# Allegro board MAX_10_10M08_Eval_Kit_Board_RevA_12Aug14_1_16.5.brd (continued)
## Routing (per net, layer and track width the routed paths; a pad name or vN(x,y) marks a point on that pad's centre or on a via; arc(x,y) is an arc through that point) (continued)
LED1: length 41.6
  TOP w0.16: U2.132 21.85,48.75 21.35,48.25 18.75,48.25 16.3,45.8 16.3,37.3 6.7,27.7 D1.2
LED2: length 40.2
  TOP w0.16: U2.134 21.8,47.75 21.65,47.9 19,47.9 16.8,45.7 16.8,37.1 8.5,28.8 D2.2
LED3: length 39
  TOP w0.16: D3.2 10.3,29.9 17.3,36.9 17.3,45.6 19.25,47.55 21.45,47.55 21.75,47.25 U2.135
LED4: length 35.3
  TOP w0.16: U2.140 19.25,44.75 17.8,43.3 17.8,36.7 12.1,31 D4.2
LED5: length 34.1
  TOP w0.16: U2.141 21.85,44.25 21.7,44.4 19.6,44.4 18.3,43.1 18.3,36.5 13.9,32.1 D5.2
NCONFIG: length 73.1
  TOP w0.16: SW2.4 SW2.3 37.15,75.45 36.1,74.4 v1(11.3,74.4) ; v1(22.6,62.7) 24.4,60.9 24.4,58.6 25.1,57.9 25.1,51.2 24.15,50.25 U2.129 21.16,50.25 R53.1
  BOTTOM w0.16: v1(22.6,62.7) 19.9,65.4 15.1,65.4 11.3,69.2 v1(11.3,74.4)
Net_66: length 0.7
  L2_GND w1.2: 36.3,24.1 36.3,24.8
OSC_OUT: length 4.1
  TOP w0.16: U2.27 37.75,36.89 X1.3
RESET_N: length 182.9
  TOP w0.16: SW1.4 SW1.3 44.8,78.05 v1(44.8,76.8) 44.8,75.6 42.9,73.7 v1(10.6,73.7) ; v1(14.2,45) 14.2,49.1 17.45,52.35 20.35,52.35 21.11,53.11 R72.2 21.66,54.25 U2.121 24.15,54.25 24.7,54.8 24.7,57.7 24,58.4 24,60.5 v1(22.6,61.9)
  BOTTOM w0.16: v1(10.6,73.7) 10.6,69.1 14.7,65 19.5,65 v1(22.6,61.9) ; J2.3 27.41,22.61 25.8,21 13.2,21 10.3,23.9 10.3,41.1 v1(14.2,45) ; v1(44.8,76.8) 56.8,76.8 62,71.6 62,44.9 61.4,44.3 59.2,44.3 58.02,45.48 J11.5
SWITCH 1: length 90.3
  TOP w0.16: v1(18.7,53.5) 19.6,54.4 21.2,54.4 21.55,54.75 U2.120 ; v1(46.4,9.2) 46.4,10.86 SW3.12
  BOTTOM w0.16: v1(18.7,53.5) 17.4,53.5 7.9,44 7.9,22.1 12,18 40.3,18 41.8,16.5 41.8,11.9 44.5,9.2 v1(46.4,9.2) R69.2
SWITCH 2: length 90.5
  TOP w0.16: v1(15.4,48.4) 15.4,48.9 18.15,51.65 20.75,51.65 21.85,52.75 U2.124 ; v1(48.9,9.2) 48.9,10.9 SW3.11
  BOTTOM w0.16: R68.2 v1(48.9,9.2) 48.3,9.8 44.6,9.8 42.2,12.2 42.2,16.8 40.5,18.5 12.2,18.5 8.3,22.4 8.3,42.7 14,48.4 v1(15.4,48.4)
SWITCH 3: length 91
  TOP w0.16: U2.127 21.45,51.25 21.15,50.95 19.25,50.95 v1(16.1,47.8) ; v1(51.4,9.2) 51.4,10.88 SW3.10
  BOTTOM w0.16: R67.2 v1(51.4,9.2) 50.3,10.3 44.8,10.3 42.6,12.5 42.6,17.1 40.7,19 12.4,19 8.7,22.7 8.7,42.4 14.1,47.8 v1(16.1,47.8)
SWITCH 4: length 91.7
  TOP w0.16: SW3.9 53.9,10.84 v1(53.9,9.2) ; U2.130 21.75,49.75 20.95,48.95 18.25,48.95 16.5,47.2 v1(15.4,47.2)
  BOTTOM w0.16: R66.2 v1(53.9,9.2) 52.3,10.8 45,10.8 43,12.8 43,17.4 40.9,19.5 12.6,19.5 9.1,23 9.1,42.1 14.2,47.2 v1(15.4,47.2)
SWITCH 5: length 92.9
  TOP w0.16: SW3.8 56.5,10.9 v1(56.5,9.2) ; U2.131 21.8,49.25 21.15,48.6 18.5,48.6 16.5,46.6 v1(16.1,46.6)
  BOTTOM w0.16: R65.2 v1(56.5,9.2) 54.4,11.3 45.2,11.3 43.4,13.1 43.4,17.7 41.1,20 12.8,20 9.5,23.3 9.5,41.8 14.3,46.6 v1(16.1,46.6)
TCK: length 94.1
  TOP w0.16: U2.18 33.25,42.05 v1(33.3,42.1)
  BOTTOM w0.16: J10.1 R62.2 64.49,78.81 69,74.3 69,35.1 67.1,33.2 63.2,33.2 57.76,38.64 39.76,38.64 37.5,40.9 34,40.9 33.3,41.6 v1(33.3,42.1)
TDI: length 108.2
  TOP w0.16: v1(33.9,42.7) 33.9,41.9 33.75,41.75 U2.19 ; v1(67.2,75) 56.3,75 53.6,77.7 53.6,82.3 52.34,83.56 J10.9
  BOTTOM w0.16: J10.9 53.6,82.34 R54.1 ; v1(33.9,42.7) 33.9,41.7 34.35,41.25 37.65,41.25 39.94,38.96 58.04,38.96 63.4,33.6 66.9,33.6 68.6,35.3 68.6,73.6 v1(67.2,75)
TDO: length 90.6
  TOP w0.16: v1(34.5,42.1) 34.25,41.85 U2.20
  BOTTOM w0.16: v1(34.5,42.1) 35,41.6 37.8,41.6 40.12,39.28 58.32,39.28 63.6,34 66.7,34 68.2,35.5 68.2,73 61.26,79.94 61.26,82.3 J10.3
TMS: length 107.4
  TOP w0.16: J10.5 57.42,83.58 58.7,82.3 58.7,77.5 60,76.2 v1(69.1,76.2) ; U2.16 32.25,41.95 v1(32.1,42.1)
  BOTTOM w0.16: v1(69.1,76.2) 69.1,75.3 69.4,75 69.4,34.9 67.3,32.8 63,32.8 57.48,38.32 39.58,38.32 37.35,40.55 33.65,40.55 v1(32.1,42.1) ; R55.1 56.2,82.38 J10.5
VREF_2.5V: length 8.8
  TOP w0.28: U2.5 26.75,41.75 27,42 v1(27,42.8)
  BOTTOM w0.28: v1(27,42.8) 27,43.29 C12.2
  BOTTOM w0.35: C61.2 R74.2 ; C61.2 28.21,43.91 27.99,43.69 C12.2 ; C61.2 28.21,47.06 U5.2
VREFB1N0: length 56.3
  TOP w0.16: v1(32.7,42.7) 32.75,42.65 U2.17
  BOTTOM w0.16: J8.38 72.9,26.42 72.9,28.3 72.2,29 65.6,29 56.92,37.68 39.22,37.68 37.05,39.85 33.05,39.85 31,41.9 31,43 31.3,43.3 32.1,43.3 v1(32.7,42.7)
VREFB2N0: length 39.8
  TOP w0.16: U2.30 39.25,41.75 v1(38.8,42.2) ; v1(63.4,41) 66.5,44.2 72.84,44.2 J8.22
  BOTTOM w0.16: v1(38.8,42.2) 40.1,40.9 43.5,40.9 44,40.4 62.71,40.4 v1(63.4,41)
VREFB3N0: length 73
  TOP w0.16: U2.48 44.24,48.21 45.81,48.21 v1(46.3,48.7) ; J8.2 72.84,69.6 v1(66.3,69.6)
  BOTTOM w0.16: v1(46.3,48.7) 52.3,42.7 63.5,42.7 64.6,41.6 64.6,36.1 64.9,35.8 65.9,35.8 66.5,36.4 66.5,43 66.3,43.2 v1(66.3,69.6)
VREFB4N0: length 46.9
  TOP w0.16: v1(42.9,54.7) 42.95,54.75 U2.61 ; J8.33 72.9,31.56 72.9,33.4 72.2,34.1 68.7,34.1 v1(65.9,36.9)
  BOTTOM w0.16: v1(42.9,54.7) 53.7,43.9 64.1,43.9 65.9,42.1 v1(65.9,36.9)
VREFB5N0: length 138.2
  TOP w0.16: v1(46.5,72.5) 46.5,69.3 45.7,68.5 42.6,68.5 38.75,64.65 U2.80
  BOTTOM w0.16: J9.38 7.5,28.14 7.5,44.3 17.29,54.09 24.59,54.09 25.2,54.7 25.2,57.99 25.1,58.09 25.1,58.1 24.5,58.7 24.5,60.95 25.15,61.6 26.8,61.6 27.2,61.2 27.2,59.9 28.3,58.8 33.3,58.8 34,59.5 34,64 30,68 16.1,68 14.5,69.6 14.5,71.6 17,74.1 37.6,74.1 39.2,72.5 v1(46.5,72.5)
VREFB6N0: length 37
  TOP w0.16: v1(30.3,60.9) 30.25,60.95 U2.97
  BOTTOM w0.16: v1(30.3,60.9) 30.7,61.3 30.7,64 30.2,64.5 26.1,64.5 22,60.4 18.5,60.4 8,70.9 J9.2
VREFB7N0: length 23.7
  TOP w0.16: v1(20.7,58.4) 21.05,58.75 U2.112
  BOTTOM w0.16: v1(20.7,58.4) 18.6,58.4 5.7,45.5 J9.22
VREFB8N0: length 40.2
  TOP w0.16: U2.123 21.8,53.25 20.55,52 17.8,52 14.8,49 14.8,36.5 6.2,27.9 6.2,27.1 5.5,26.4 3.22,26.4 J9.37
N15317190: length 1.4
  TOP w0.2: R75.2 30.35,9.74 U1.12
N15317205: length 1.2
  TOP w0.2: U1.11 30.85,10.24 R76.2
N15317224: length 1.4
  TOP w0.2: R77.2 31.35,9.64 U1.10
N16795142: length 31.6
  TOP w0.16: R17.2 59.19,32.91 59.5,32.6 59.5,27.7 61.7,25.5 61.7,21 58.3,17.6 58.3,15 57.8,14.5 49.64,14.5 J6.2
N16798349: length 13.6
  TOP w0.16: R19.2 58.7,27.3 59.2,26.8 59.2,21 57.04,18.84 J7.2
N16798444: length 10.1
  TOP w0.16: J7.3 59.58,14.62 61.75,12.45 R16.2 65.77,12.45 R94.2
N16825621: length 1.7
  TOP w0.16: U2.136 21.16,46.75 R51.1
N16825626: length 1.7
  TOP w0.16: U2.138 21.16,45.75 R52.1
N16827450: length 1.3
  TOP w0.16: R57.2 D1.1
N16827455: length 1.3
  TOP w0.16: R58.2 D2.1
N16827460: length 1.3
  TOP w0.16: R59.2 D3.1
N16827465: length 1.3
  TOP w0.16: R60.2 D4.1
N16856284: length 1.3
  TOP w0.16: R61.2 D5.1
N16879493: length 4.2
  TOP w0.16: U3.3 22.02,31.87 C22.1 R78.1 R10.1
N16880012: length 4.2
  TOP w0.16: U3.5 22.02,29.33 C19.1 R79.1 R8.1
N16880301: length 4.2
  TOP w0.16: U3.10 31.18,29.33 C21.1 R80.1 R7.1
N16880631: length 4.2
  TOP w0.16: R9.1 R81.1 C20.1 31.18,31.87 U3.12
N16880930: length 4.2
  TOP w0.16: U4.3 47.32,31.87 C25.1 R82.1 R20.1
N16881114: length 4.2
  TOP w0.16: U4.5 47.32,29.33 C23.1 R83.1 R18.1
N16881411: length 4.2
  TOP w0.16: R19.1 R84.1 C26.1 56.48,29.33 U4.10
N16881659: length 4.2
  TOP w0.16: U4.12 56.48,31.87 C24.1 R85.1 R17.1
N16906288: length 4.2
  TOP w0.16: U2.3 25.75,42.35 v1(25.2,42.9)
  BOTTOM w0.16: v1(25.2,42.9) R73.2 C46.2
N16996005: length 9.2
  TOP w0.16: U2.6 27.25,39.86 26.89,39.5 26.2,39.5 25.4,38.7 C53.1 25.39,38.2 24.9,38.2 24.7,38 24.7,36.3 24.01,35.61 R86.2
N16998422: length 20.8
  TOP w0.16: C54.1 v1(26.5,39) 26.9,39 27.75,39.85 U2.7 ; R87.2 21,26.69 v1(21,25.9)
  BOTTOM w0.16: v1(26.5,39) 24.4,36.9 24.4,27.2 23.1,25.9 v1(21,25.9)
N16998544: length 19.5
  TOP w0.16: R88.2 v1(33,26.7) ; C55.1 v1(27.6,39) 28.25,39.65 U2.8
  BOTTOM w0.16: v1(33,26.7) 30.7,26.7 28.15,29.25 28.15,38.45 v1(27.6,39)
N16998676: length 11.5
  TOP w0.16: R89.2 v1(33,34.5) ; U2.10 29.25,39.6 28.7,39.05 v1(28.7,39) C56.1
  BOTTOM w0.16: v1(28.7,39) 29.25,38.45 29.25,35.45 30.2,34.5 v1(33,34.5)
N16999504: length 32.4
  TOP w0.16: C57.1 v1(29.8,39) 29.75,39.05 U2.11 ; R90.1 45,34.5 44,33.5 44,29.1 43.3,28.4 36.2,28.4 34.9,29.7 34.9,33.7 v1(33.1,35.5)
  BOTTOM w0.16: v1(33.1,35.5) 30.8,35.5 30.35,35.95 30.35,38.45 v1(29.8,39)
N16999867: length 28.2
  TOP w0.16: R91.1 v1(45.5,26.7) ; U2.12 30.25,39.65 v1(30.9,39) C58.1
  BOTTOM w0.16: v1(45.5,26.7) 35.4,26.7 33.7,28.4 33.7,36.6 33.2,37.1 32.8,37.1 v1(30.9,39)
N17000151: length 40.8
  TOP w0.16: U2.13 30.75,39.91 31.66,39 v1(32,39) C59.1 ; R92.1 v1(58.3,26.7)
  BOTTOM w0.16: v1(58.3,26.7) 49.9,26.7 48.5,28.1 45.8,28.1 45.2,27.5 35.3,27.5 34.1,28.7 34.1,36.9 v1(32,39)
N17000639: length 47.8
  TOP w0.16: v1(33.9,38.2) 33.89,38.21 C60.1 33.1,38.7 32.2,39.6 31.55,39.6 31.25,39.9 U2.14 ; R93.1 v1(58.3,34.5) 60.1,32.7 v1(60.1,28.6)
  BOTTOM w0.16: v1(33.9,38.2) 34.52,37.58 34.52,28.98 35.6,27.9 44.9,27.9 45.6,28.6 v1(60.1,28.6)
N17005599: length 9.7
  TOP w0.16: R94.1 69.6,13.5 67.75,15.35 R16.1 64.41,15.41 R15.1
N167529890: length 1.3
  TOP w0.16: R2.1 D6.1
N168590211: length 2.3
  TOP w0.28: U2.4 26.25,42.05 v1(26.3,42.1)
  BOTTOM w0.35: L3.2 26.3,41.45 v1(26.3,42.1)

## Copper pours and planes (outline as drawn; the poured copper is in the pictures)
3.3V on TOP (solid shape): 18.4,22.3 19.5,21.2 36.1,21.2 38.5,18.8 38.5,14.3 39.1,13.7 39.1,10.8 39.4,10.5 40.9,10.5 40.9,7.5 33.4,7.5 33.21,7.31 31.75,7.31 31.75,8.55 31.8,8.6 32.7,8.6 35,10.9 35,16.6 34.6,17 17.6,17 15.9,18.7 15.9,25.2 16.31,25.61 18.4,25.61
AGND on L2_GND: outline of 92 points within 14.4,10.2 72.3,72.1
DGND on TOP (solid shape): 34.6,11.4 34.2,11 29.5,11 29.5,13.8 34.6,13.8
DGND on TOP (solid shape): 23.5,6.5 21.35,6.5 21.35,10.4 22.13,10.4 22.13,11.2 23.5,11.2
DGND on TOP (solid shape): 30.3,7.13 30.34,7.05 30.42,7.01 30.43,7.01 30.51,7.05 30.55,7.13 30.55,8.5 31.62,8.5 31.62,7.25 31.69,7.18 36.3,7.18 36.3,3.45 32.95,3.45 32.6,3.8 32.6,6.68 30.49,6.68 30.49,6 29.71,6 29.71,6.55 29.58,6.68 29.08,6.68 29,6.6 29,5.8 27.3,5.8 27.3,7.5 28.7,7.5 28.7,7.2 28.72,7.18 29.6,7.18 29.6,8.5 30.3,8.5
DGND on L2_GND: 0.5,0.5 0.5,88.4 75.7,88.4 75.7,0.5 ; 1 cut-out
VBUS_5V on TOP (solid shape): 29,12.4 29,10.1 29.4,9.7 29.8,9.7 29.99,9.51 29.99,8.7 29.4,8.7 29.4,8.3 28.7,8.3 28.7,7.9 26.8,7.9 26.8,9.8 25.2,11.4 21.67,11.4 21.67,10.62 19.69,10.62 19.69,13.9 27.5,13.9
VBUS_5V on L3_PWR: 60.9,1.5 60.9,5.74 59.54,7.1 26.2,7.1 26.2,9.36 26.54,9.7 40.34,9.7 41.7,11.06 41.7,16.24 40.74,17.2 27.84,17.2 27.5,17.54 27.5,24.3 42.06,24.3 42.7,23.66 42.7,20.96 44.2,19.46 44.2,14.46 44.96,13.7 59.36,13.7 63.06,10 70.54,10 71.1,10.56 71.1,18.14 68.7,20.54 68.7,23.36 69.34,24 72.04,24 72.5,24.46 72.5,25.94 72.04,26.4 67.74,26.4 58.9,35.24 58.9,51.26 59.64,52 74.7,52 74.7,1.5
VCC_CORE on TOP (solid shape): 41.1,11 39.5,11 39.5,16.1 41.1,16.1
VCC_CORE on L3_PWR: 16.84,7.1 15,8.94 15,11.34 13.74,12.6 7.24,12.6 6.4,13.44 6.4,33.26 12,38.86 12,41.64 11.34,42.3 1.5,42.3 1.5,87.4 74.7,87.4 74.7,52.2 59.56,52.2 58.7,51.34 58.7,35.3 44.16,35.3 43.3,34.44 43.3,29.24 43.06,29 36.84,29 36.2,29.64 36.2,39.3 41.54,39.3 43.8,41.56 43.8,42.96 44.2,43.36 44.2,48.64 43.44,49.4 42.64,49.4 42.3,49.74 42.3,53.06 45.2,55.96 45.2,61.44 43.64,63 39.34,63 38.2,64.14 38.2,71.94 35.84,74.3 15.16,74.3 13.1,72.24 13.1,68.66 15.06,66.7 23.86,66.7 24.8,65.76 24.8,63.44 23.3,61.94 23.3,58.76 24.4,57.66 24.4,57.24 21.5,54.34 21.5,41.36 22.8,40.06 22.8,38.84 22.26,38.3 17.46,38.3 11,31.84 11,24.66 21.76,13.9 34,13.9 34,17 40.66,17 41.5,16.16 41.5,11.14 40.26,9.9 26.46,9.9 26,9.44 26,7.1
VCC_IO on TOP (solid shape): 34.6,14.2 30.6,14.2 30.6,16.4 34.6,16.4
VCC_IO on L3_PWR: outline of 106 points within 11.2,14.1 45,74.1
VCC_IO8 on BOTTOM (solid shape): 22.5,52.7 22.5,51.5 22.7,51.3 24.4,51.3 24.4,49.8 24.2,49.6 22.7,49.6 22.5,49.4 22.5,45.7 22.7,45.5 24.4,45.5 24.4,44.6 19.4,44.6 18.8,45.2 18.8,52.5 19.5,53.2 22,53.2
VCC_IO8 on L3_PWR: 1.5,1.5 1.5,42.1 11.26,42.1 11.8,41.56 11.8,38.94 6.2,33.34 6.2,13.36 7.16,12.4 13.66,12.4 14.8,11.26 14.8,8.86 16.76,6.9 59.46,6.9 60.7,5.66 60.7,1.5
VCCA_3.3V on L3_PWR: outline of 92 points within 14.4,10.2 72.3,72.1
N15317661 on TOP (solid shape): 19.2,10.3 19.45,10.05 19.45,6.5 17.9,6.5 17.9,11.55 19.2,11.55

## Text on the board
BOTTOM: LAYER:4 | BOTTOM
Ref Des/Silkscreen Bottom: IO6 | GND | 88 | 89 | 92 | 93 | 99 | 101 | 105 | 106 | 117 | 110 | 111 | NC | IO8 | 123 | 97 | 90 | 91 | 96 | 98 | 100 | 102 | 112 | 118 | 119 | 113 | 114 | IO5 | 80 | IO3 | 60 | 59 | 56 | 55 | 47 | 46 | 43 | 41 | IO2 | 33 | 32 | IO4 | 61 | IO1A | 48 | 58 | 57 | 52 | 50 | 45 | 44 | 39 | 38 | 30 | 29 | 28 | 23 | 17 | RoHS
User.Comments: ADD FOUR SMT MARK | ON TOP LAYER
TOP: LAYER:01 | TOP
Ref Des/Silkscreen Top: IO6 | GND | 88 | 89 | 92 | 93 | 99 | 101 | 105 | 106 | 117 | 110 | 111 | NC | IO8 | 123 | 97 | 90 | 91 | 96 | 98 | 100 | 102 | 112 | 118 | 119 | 113 | 114 | IO5 | 80 | IO3 | 60 | 59 | 56 | 55 | 47 | 46 | 43 | 41 | IO2 | 33 | 32 | IO4 | 61 | IO1A | 48 | 58 | 57 | 52 | 50 | 45 | 44 | 39 | 38 | 30 | 29 | 28 | 23 | 17
DIMENSION: 1. No. of layers:  4 | 2. Finished board size:  88.9mm x 76.2mm | 3. Base material: Generic FR-4, glass epoxy material must conform to UL94V-0. | 4. Finished board thickness & tolerance: 1.6 mm +/-10% | 5. Bow&twist: <=0.7% | 6. All hole sizes are specified after plating and marked. | 7. Apply white, non-conductive silkscreen legend to top and bottom sides | 8. The layer order is as shown in the figure. | 9. Add teardrops to all inner layer positive pads on holes as needed. | 10. Fabricate board per IPC-6012A. | 11. Surface finish:Both HASL and ENIG are OK, the cheaper option is preferred. | 12. Green soldermask on top and bottom sides of board, LPI applied over bare copper. | 13. PCB vendor must print date, ID code, UL rating on bottom silkscreen layer | 14. Test short/open against IPC-D-356A netlist provided by Axelsys. DGND and AGND | 15. Fabricate PCB using the Gerber data provided. If any Gerber edits are | 16. Vendor strictly dispose according to customer's original Gerber file, | 17. Refer to next page for the panelization. | TECHNICAL SPECIFICATION: | Thickness in hole wall: 20um (min) | of the board. No ink is allowd in holes and on pads. | No soldermask is allowed on solder pad. Must conform to IPC-SM-840. | of boards. | performed. A copy of the edited data must be provided to Axelsys no later | than 24 hours after fabrication release. | without any modifications. If any, immediately inform customer for confirmation. | are shorted intendedly on layer 2 that can be ignored. | PCB tolerance specification: | Outline dimension tolerance | Hole diameter | tolerance | Slot | PTH/NPTH | PTH | NPTH | 100<L<=300 | D=0.1-0.8          +/-0.08 | D=0.81-1.6         +/-0.10 | D=1.61-5.0         +/-0.15 | Position tolerance +/-0.076 | L<=100 | L>300 | L>2W+0.15         (+/-0.08)X(+/-0.08) | L<2W+0.15         (+/-0.10)X(+/-0.10) | L>2W+0.05         (+/-0.05)X(+/-0.05) | L<2W+0.05         (+/-0.08)X(+/-0.08) | NC routing | TOP | L2_GND | L3_PWR | BOTTOM | +/-0.20 | +/-0.25 | +/-0.30 | (+/-0.13)X(+/-0.13) | Layer name: | core | prepreg | UNIT:mm | 0.5oz+plating | 0.2 | As required | 1oz | thickness | Stackup | (mm) | copper | 2*2113 | material | Trace Width | Single-ended impedance | (Ohms) | Impedance | 0.13 | Differential impedance | Space(mm) | Design | 100+/-10%
User.13: DESIGNER:LENNON WANG | CHECKER:LENNON WANG | DATE:12AUG14 | REV | COMPANY NAME: | PROJECT NAME: | PROJECT NUMBER:
User.14: DESIGNER:LENNON WANG | CHECKER:LENNON WANG | DATE:12AUG14 | COMPANY NAME: | PROJECT NAME: | PROJECT NUMBER: | REV
User.15: PROTOTYPE AREA | MAX R 10 10M08 Eval | Kit Board REV A | P/N:100-0991402-A1
User.16: 2014 | c | Designed by Axelsys LLC | www.axelsys.com | Copyright | FAB P/N:140-0991402-A1 | REV A | Made in China
User.17: DESIGNER:L.WANG | CHECKER:L.WANG | DATE:12AUG14 | SIZE | C | PROJECT NAME | MAX R 10 10M08 Eval Kit Board | SHEET | REV | A
User.18: PASTEMASK | TOP
User.26: ASSEMBLY(BOTTOM) | ASSEMBLY DRAWING NUMBER | 2/2
User.27: ASSEMBLY(TOP) | ASSEMBLY DRAWING NUMBER | 1/1
User.34: LAYER:02 | L2_GND
User.35: LAYER:03 | L3_PWR
User.36: LAYER:04 | L4_SIG
User.37: LAYER:05 | L5_VCC
User.38: LAYER:06 | L6_GND
User.39: LAYER:07 | L7_SIG
User.40: LAYER:08 | L8_SIG
User.41: LAYER:09 | L9_GND
User.42: LAYER:10 | L10
User.43: LAYER:11 | L11
User.44: LAYER:12 | L12
User.45: LAYER:13 | L13 | PRIMARY-SIDE | ASSEMBLY | SECONDARY-SIDE | FAB DRAWING | FAB NUMBER | 140-0991402-A1 | 1/1 | 130-0991402-A1 | FIGURE | SIZE | 0.254 | 0.3048 | 1.00 | 1.016 | 0.90 | 3.25 | DRILL CHART: TOP to BOTTOM | ALL UNITS ARE IN MILLIMETERS | PLATED | NON-PLATED | QTY | 171 | 80 | 223 | 8 | 2 | 4
